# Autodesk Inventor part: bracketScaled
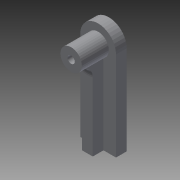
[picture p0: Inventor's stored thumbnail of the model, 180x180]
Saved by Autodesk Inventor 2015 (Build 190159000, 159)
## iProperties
Created: 2015-02
Part Number: bracketScaled
Material: ABS Plastic
Document SubType Name: Modeling
Designer: sungeun
Density: 1.06 g/cm^3
Appearance: Smooth - White
Author: sungeun
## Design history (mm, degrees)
feature "bracket"
feature "MeshFeature1"
body "Solid1"
